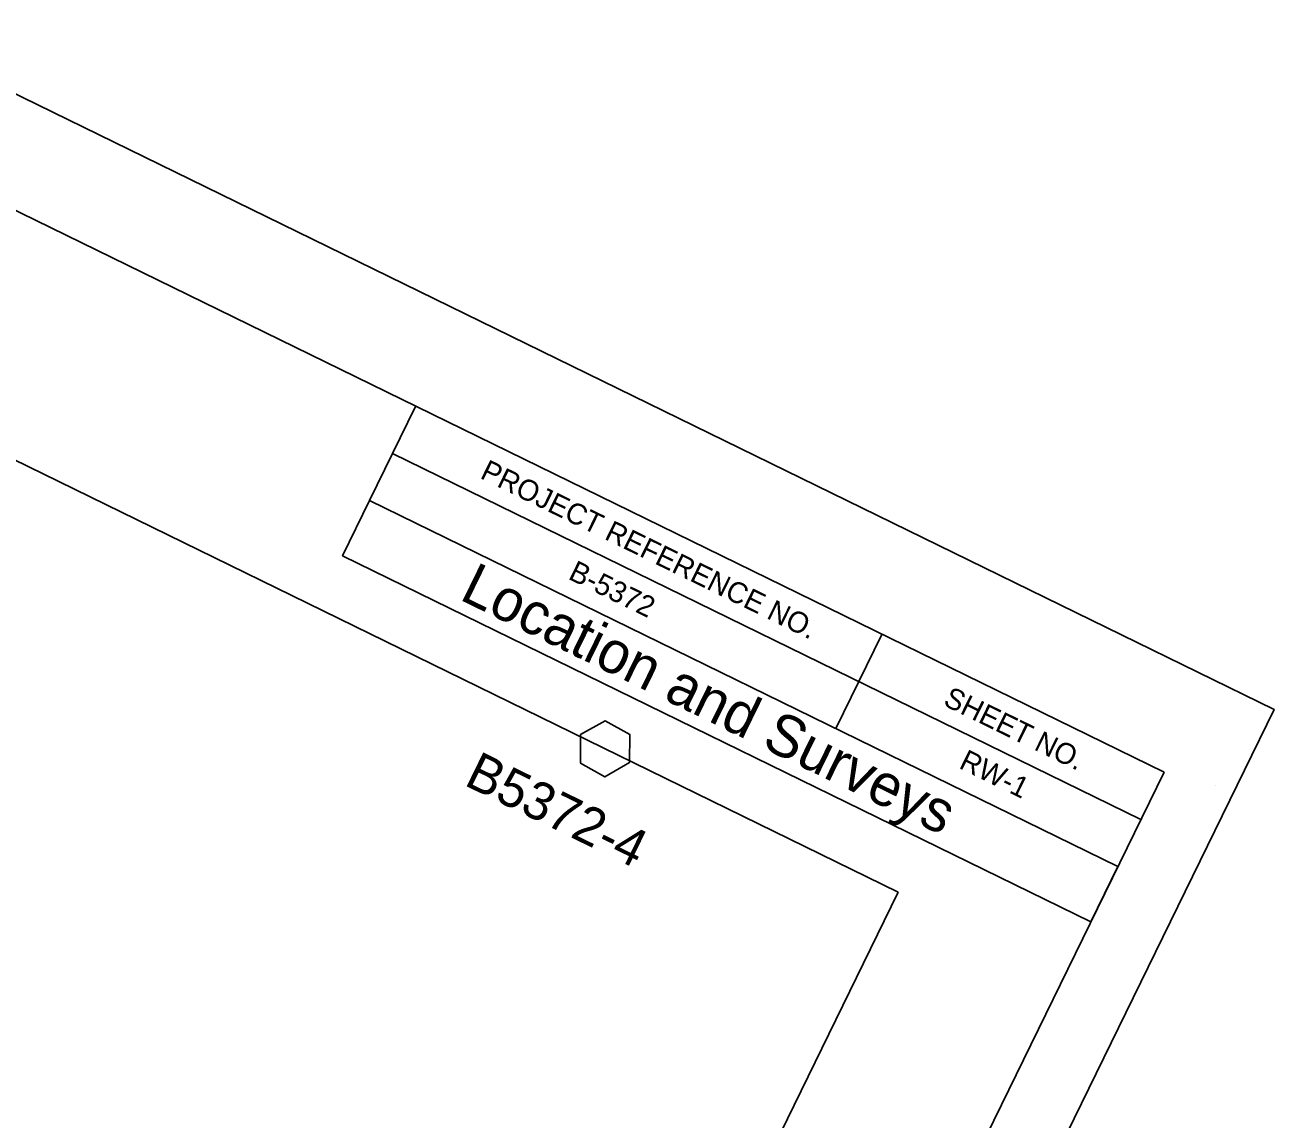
# Model space of a CAD drawing. Extents: x 1517485 to 1521905, y 636528 to 640355.
# Drawn here: x 1521245 to 1521905, y 638500 to 639078 of the extents above; entities that cross this region are included whole.
import ezdxf

# ---------------------------------------------------------------- set-up
doc = ezdxf.new("R2010")
doc.units = 0
for name, color, linetype in [('CTL Primary Horizontal and Vertical CELL', 7, 'Continuous'), ('CTL Primary Horizontal and Vertical Text', 7, 'Continuous'), ('CTL Sheet Border CELL', 7, 'Continuous'), ('Scratch_Level_3', 7, 'Continuous'), ('Sheet Plot Border Outside CELL', 7, 'Continuous')]:
    doc.layers.add(name, color=color, linetype=linetype)

msp = doc.modelspace()

# ---------------------------------------------------------------- linework, layer by layer
at = {"layer": 'CTL Primary Horizontal and Vertical CELL'}
msp.add_line((1521551.57, 638695.6), (1521551.57, 638695.6), dxfattribs=at)
msp.add_lwpolyline([(1521538.65, 638703.09), (1521551.65, 638710.34), (1521564.65, 638703.19), (1521564.45, 638688.29), (1521551.45, 638680.74), (1521538.65, 638687.99)], close=True, dxfattribs=at)
at = {"layer": 'CTL Sheet Border CELL'}
for p, q in [((1521451.39, 638876.66), (1521427.06, 638826.93)), ((1521439.22, 638851.78), (1521834.97, 638658.23)), ((1521697.94, 638756.08), (1521673.61, 638706.34)), ((1521905.33, 638716.38), (1521905.33, 638716.38)), ((1521874.55, 638676.12), (1521874.55, 638676.12)), ((1521874.55, 638676.12), (1521874.55, 638676.12))]:
    msp.add_line(p, q, dxfattribs=at)
for points in [[(1521847.18, 638683.19), (1518862.95, 640142.72), (1517841.29, 638053.77), (1520825.52, 636594.25)], [(1521427.06, 638826.93), (1521822.81, 638633.37), (1521808.49, 638604.09), (1521412.74, 638797.64)]]:
    msp.add_lwpolyline(points, close=True, dxfattribs=at)
at = {"layer": 'Scratch_Level_3'}
for p, q in [((1520770.84, 639077.45), (1521706.65, 638619.76)), ((1521706.65, 638619.76), (1520952.83, 637078.47))]:
    msp.add_line(p, q, dxfattribs=at)
at = {"layer": 'Sheet Plot Border Outside CELL'}
msp.add_lwpolyline([(1517484.74, 638166.53), (1520835.03, 636527.97), (1521905.33, 638716.38), (1518555.04, 640354.94)], close=True, dxfattribs=at)

# ---------------------------------------------------------------- texts
at = {"layer": 'CTL Primary Horizontal and Vertical Text'}
msp.add_text('B5372-4', height=20, rotation=333.93772, dxfattribs=at).set_placement((1521476.41, 638676.7))
at = {"layer": 'CTL Sheet Border CELL'}
for s, height, p in [('PROJECT REFERENCE NO.', 11.0736, (1521484.92, 638838.93)), ('Location and Surveys', 22.1471, (1521473.95, 638774.83)), ('B-5372', 11.074, (1521531.55, 638785.62)), ('SHEET NO.', 11.074, (1521729.83, 638718.9)), ('RW-1', 11.074, (1521738.17, 638685.64))]:
    msp.add_text(s, height=height, rotation=333.93772, dxfattribs=at).set_placement(p)

doc.saveas('drawing.dxf')
